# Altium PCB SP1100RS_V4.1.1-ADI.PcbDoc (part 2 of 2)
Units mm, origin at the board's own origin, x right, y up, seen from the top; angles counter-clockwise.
Board outline 126.12 x 87.13 mm, 4 copper layers (TopLayer, GND, PWR, BottomLayer); 154 components, 100 nets, 516 pads, 161 vias.
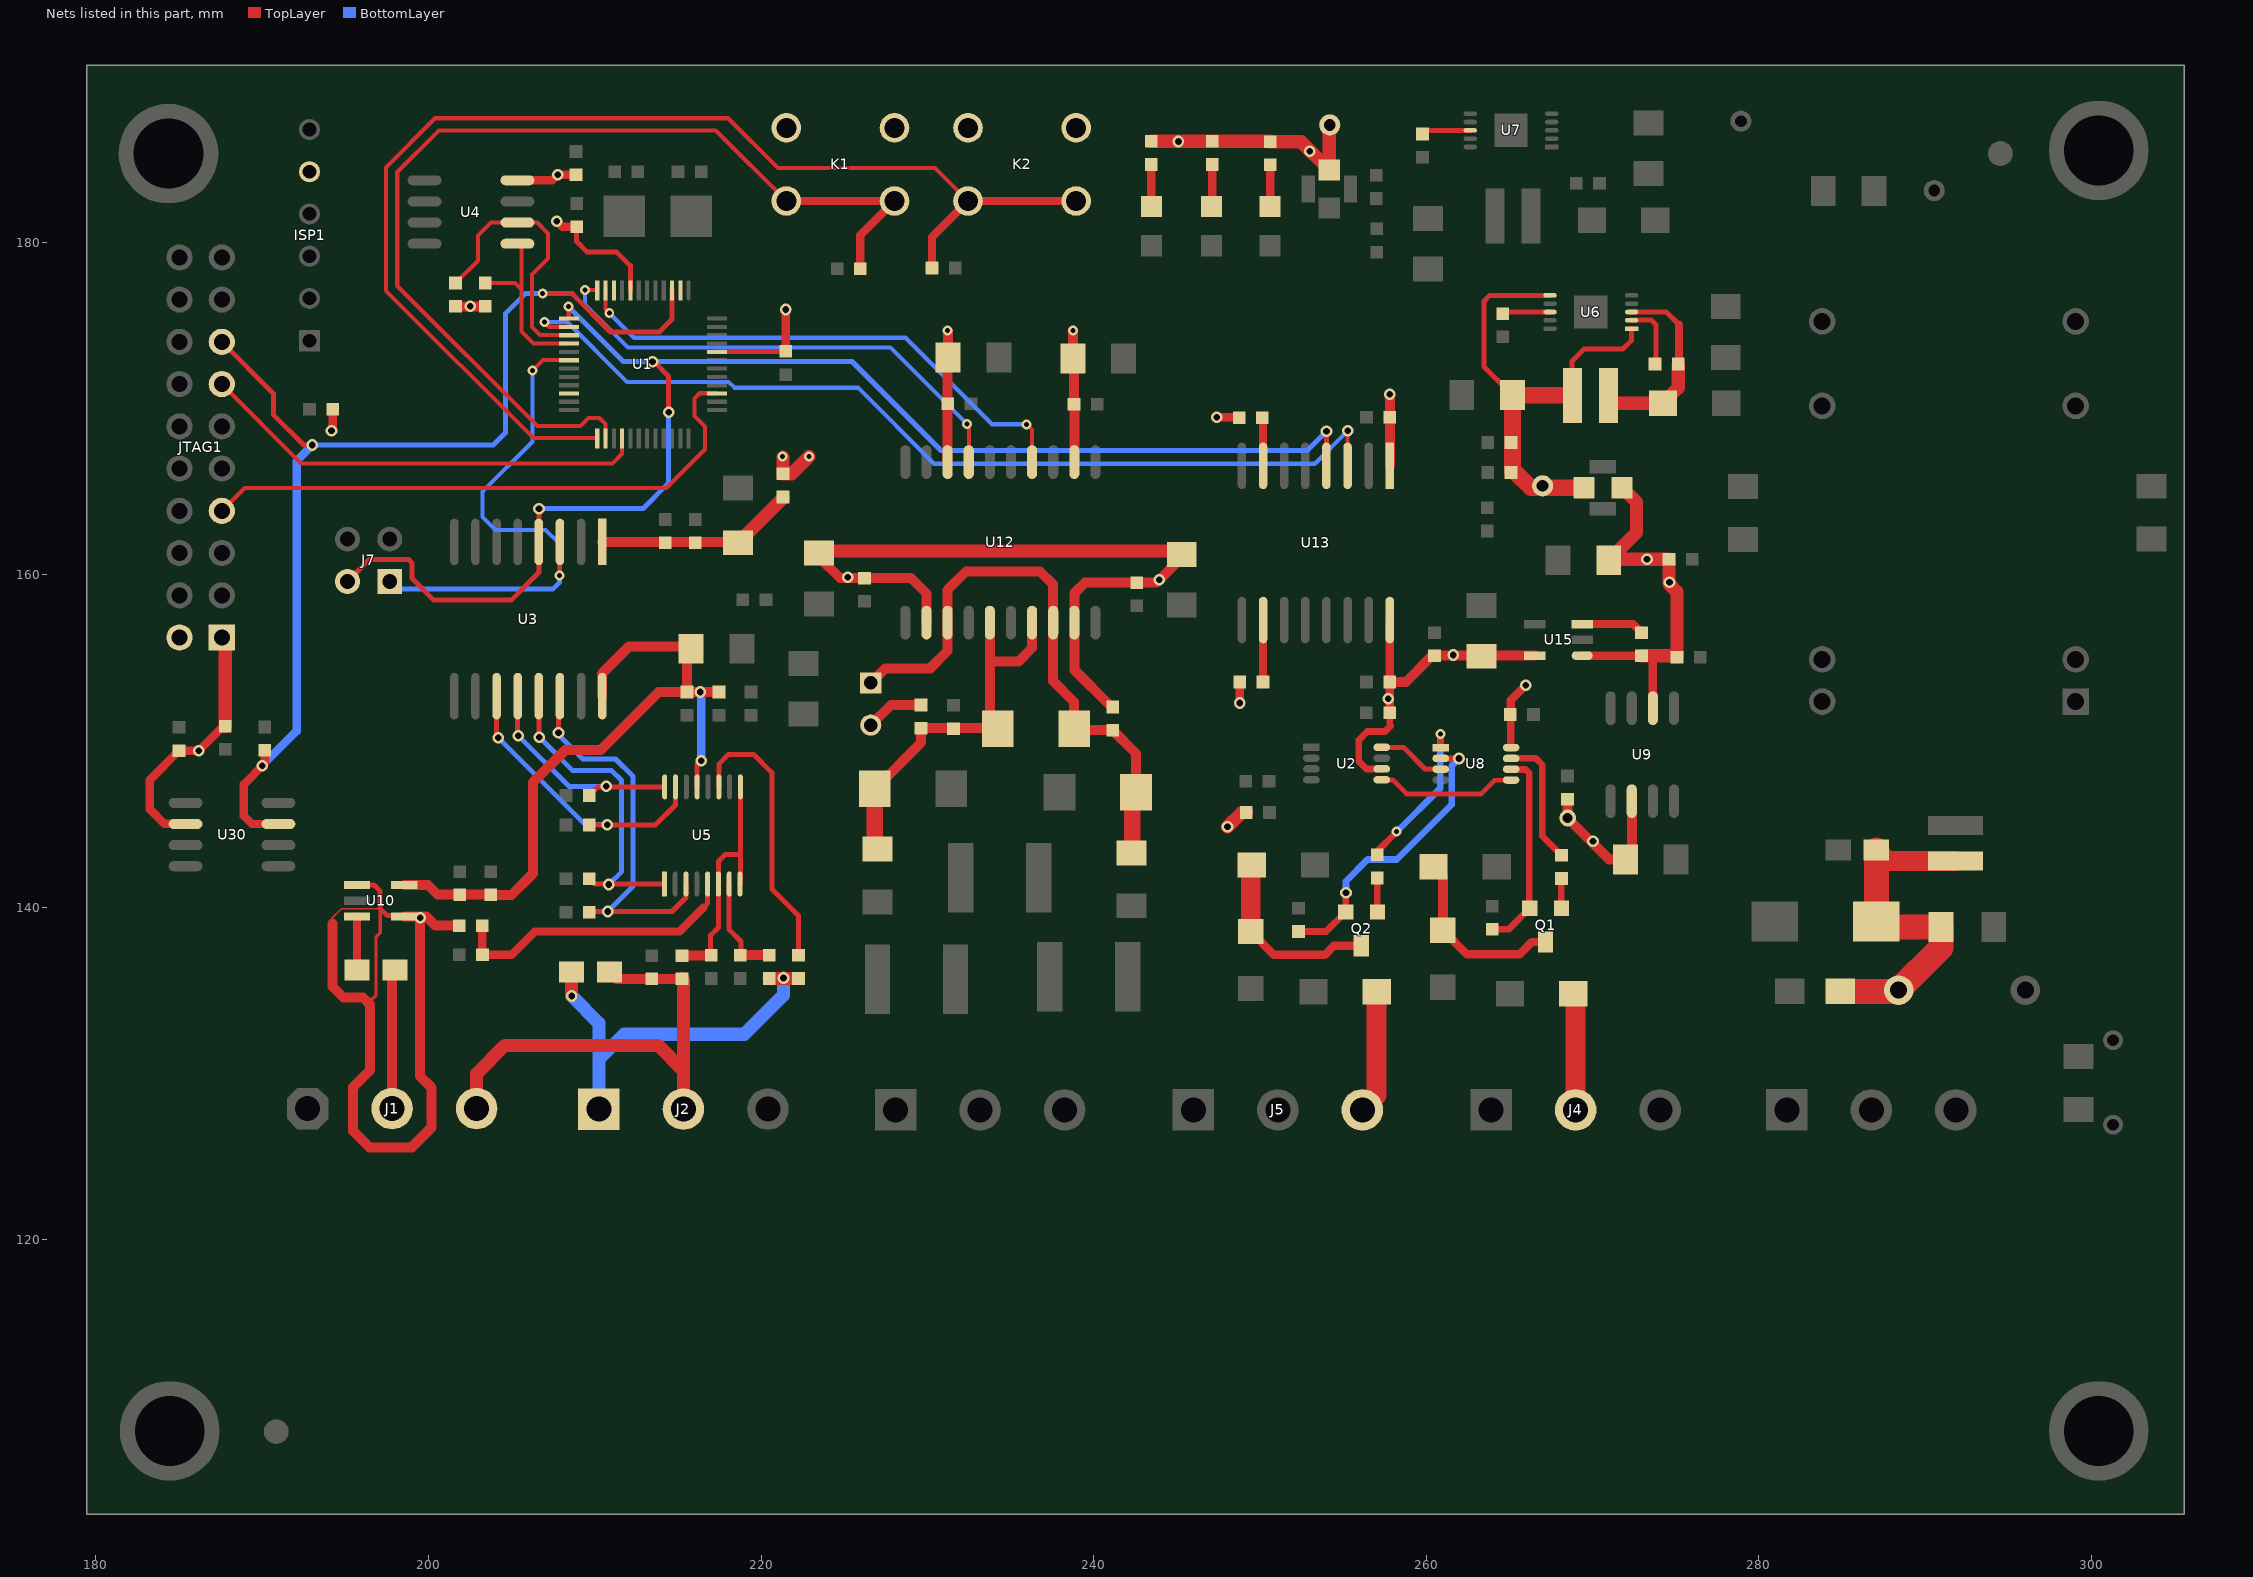
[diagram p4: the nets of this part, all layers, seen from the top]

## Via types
v1: diameter 0.7, hole 0.4, TopLayer to BottomLayer, 127 vias
v2: diameter 0.6, hole 0.3, TopLayer to BottomLayer, 30 vias
v3: diameter 1, hole 0.6, TopLayer to BottomLayer, 4 vias

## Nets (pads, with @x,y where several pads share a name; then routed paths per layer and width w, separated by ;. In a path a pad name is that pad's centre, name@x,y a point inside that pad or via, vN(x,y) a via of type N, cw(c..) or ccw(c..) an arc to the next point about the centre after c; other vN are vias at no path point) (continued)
NetC17_1: C17.1 R3.2 U5.7 | length 6.3
  TopLayer w0.3: U5.7@218.089,141.404 218.089,138.661 218.8,137.95 218.8,137.175 C17.1@218.75,137.125
  TopLayer w0.6: C17.1@218.75,137.125 220.497,137.125 R3.2@220.5,137.122
NetC18_1: C18.1 R19.2 U5.5 | length 17.7
  TopLayer w0.3: C18.1@203.247,137.153 C18.1@203.25,137.15 ; 216.538,139.988 216.789,140.239 U5.5@216.789,141.404
  TopLayer w0.5: C18.1@203.247,137.153 R19.2@203.247,138.9 ; C18.1@203.25,137.15 205,137.15 206.4,138.55 215.1,138.55 216.538,139.988
NetC19_1: C19.1 R20.2 U5.6 U5.8 U5.9 | length 15
  TopLayer w0.3: C19.1@216.972,137.097 216.975,137.1 216.975,138.325 217.439,138.789 U5.6@217.439,141.404 217.439,142.764 217.85,143.175 218.761,143.175 ; U5.8@218.739,141.404 218.761,141.426 218.761,143.175 ; U5.9@218.761,147.246 218.761,143.175
  TopLayer w0.6: R20.2@215.25,137.097 C19.1@216.972,137.097 ; C19.1@216.975,137.1 C19.1@217,137.125
NetC22_1: C22.1 U6.2 | length 4
  TopLayer w0.3: U6.2@272.318,175.306 273.543,175.306 273.805,175.044 C22.1@273.805,172.675
NetC22_2: C22.2 D49.2 L1.1 U6.3 | length 11.8
  TopLayer w0.3: U6.3@272.318,175.806 274.44,175.806 275.202,175.044
  TopLayer w0.5: C22.2@275.202,172.675 275.202,175.044
  TopLayer w0.8: L1.1@270.96,170.775 271.423,170.312 D49.2@274.236,170.312 275.157,171.233 C22.2@275.157,172.675
NetC23_1: C23.1 C51.1 FB7.1 L1.2 TP6.1 U6.1 U6.6 VA2.2 | length 29.3
  TopLayer w0.3: C23.1@265.185,170.8 263.475,172.51 263.475,176.45 263.825,176.8 U6.6@267.45,176.8 ; L1.2@268.775,170.8 268.775,172.85 269.5,173.575 271.825,173.575 272.35,174.1 U6.1@272.35,174.8
  TopLayer w1: VA2.2@265.185,166.238 C23.1@265.185,170.8 268.775,170.8 L1.2@268.8,170.775 ; VA2.2@265.375,166.15 266.292,165.233 268.76,165.233
NetC41_1: C41.1 CA11.1 D3.2 F3.2 L3.1 VR1.1 | length 21.8
  TopLayer w1.2: C41.1@287.065,143.442 287.732,142.775 L3.1@291.825,142.775
  TopLayer w1.5: F3.2@284.898,134.95 288.33,134.95 D3.2@288.405,135.025 290.952,137.572 VR1.1@290.952,138.825 287.375,138.825 CA11.1@287.05,139.15 287.065,139.165 C41.1@287.065,143.442
NetC54_1: C54.1 CA22.1 FB2.1 U9.6 | length 10.8
  TopLayer w0.6: C54.1@268.5,146.5 v3(268.5,145.375) 271,142.875 CA22.1@271.975,142.875 272.36,143.26 U9.6@272.36,146.387
  TopLayer w0.8: v1(248.05,144.85) 248.9,145.7 FB2.1@249.178,145.7
  other v1: 270.025,143.975
NetD1_2: D1.2 F1.1 Q1.3 | length 11.1
  TopLayer w0.5: F1.1@261,138.625 262.45,137.175 265.6,137.175 266.345,137.92 Q1.3@267.165,137.92
  TopLayer w0.6: D1.2@260.44,142.447 261,141.888 F1.1@261,138.625
NetD2_2: D2.2 F2.1 Q2.3 | length 11.5
  TopLayer w0.5: F2.1@249.45,138.554 250.854,137.15 253.9,137.15 254.445,137.695 Q2.3@256.098,137.695
  TopLayer w1.2: F2.1@249.45,138.554 249.45,142.482 D2.2@249.515,142.547
NetD4_2: D4.2 J4.2 | length 7
  TopLayer w1.2: D4.2@268.842,134.803 268.986,134.659 J4.2@268.986,127.823
NetD5_2: D5.2 J5.3 | length 7.5
  TopLayer w1.2: J5.3@256.159,127.823 257.017,128.681 D5.2@257.017,134.928
NetF10_1: F10.1 R41.2 T1.1 U12.13 U12.18 ZD14.1 ZD15.1 | length 36.2
  TopLayer w0.6: T1.1@226.6,153.5 227.45,154.35 230.15,154.35 231.22,155.42 U12.13@231.22,157.123 231.22,159.095 232.325,160.2 236.779,160.2 237.57,159.409 U12.18@237.57,157.123 237.57,153.605 238.825,152.35 ZD14.1@238.825,150.75 238.922,150.653 R41.2@241.15,150.653 242.55,149.253 ZD15.1@242.55,146.925 ; F10.1@242.316,142.94 F10.1@242.316,143.29
  TopLayer w1: F10.1@242.316,143.29 242.316,146.691 ZD15.1@242.55,146.925
NetF11_1: F11.1 R42.1 R76.1 U12.15 U12.17 ZD14.2 ZD16.2 | length 24.1
  TopLayer w0.6: ZD16.2@226.85,147.125 229.625,149.9 R76.1@229.625,150.775 ZD14.2@234.2,150.775 ; U12.15@233.76,157.123 233.76,154.95 ; ZD14.2@234.225,150.75 ZD14.2@234.2,150.775 ; U12.17@236.3,157.123 236.3,155.6 235.475,154.775 233.935,154.775 233.76,154.95 ; 233.76,154.95 233.76,151.215 ZD14.2@234.2,150.775
  TopLayer w1: ZD16.2@226.85,147.125 226.85,143.574 F11.1@226.949,143.475
NetLD1_A: LD1.A R18.1 | length 2.5
  TopLayer w0.5: R18.1@250.625,184.65 250.625,182.225 LD1.A@250.65,182.2
NetLD2_A: LD2.A R17.1 | length 2.5
  TopLayer w0.5: R17.1@243.475,184.675 243.475,182.191 LD2.A@243.49,182.176
NetLD3_A: LD3.A R52.1 | length 2.5
  TopLayer w0.5: LD3.A@247.115,182.151 247.125,182.161 R52.1@247.125,184.675
NetQ1_1: Q1.1 R7.1 | length 1.8
  TopLayer w0.4: Q1.1@268.13,139.952 R7.1@268.13,141.738
NetQ1_2: Q1.2 R5.1 U8.6 | length 12.1
  TopLayer w0.4: R5.1@263.975,138.675 264.948,138.675 Q1.2@266.225,139.952 266.192,139.985 266.192,148.07 265.968,148.294 U8.6@265.088,148.294
NetQ2_1: Q2.1 R13.1 | length 2
  TopLayer w0.4: Q2.1@257.063,139.727 R13.1@257.063,141.765
NetQ2_2: Q2.2 R4.1 U8.2 | length 17.5
  TopLayer w0.4: R4.1@252.325,138.55 253.981,138.55 Q2.2@255.158,139.727 255.158,140.858 v1(255.175,140.875) ; U8.2@260.858,148.944 261.969,148.944 v1(261.975,148.95)
  BottomLayer w0.4: v1(255.175,140.875) 255.175,141.575 256.475,142.875 258.225,142.875 261.525,146.175 261.525,148.5 v1(261.975,148.95)
NetR2_2: R2.2 U5.11 | length 16.9
  TopLayer w0.3: U5.11@217.461,147.246 217.461,148.611 218.05,149.2 219.55,149.2 220.65,148.1 220.65,141.1 222.25,139.5 R2.2@222.25,137.122
NetR7_2: R7.2 U8.7 | length 7.9
  TopLayer w0.4: U8.7@265.106,148.958 266.592,148.958 266.975,148.575 266.975,144.29 R7.2@268.13,143.135
NetR8_2: R8.2 U6.8 | length 2.9
  TopLayer w0.3: R8.2@264.61,175.7 264.71,175.8 U6.8@267.45,175.8
NetR11_2: R11.2 U7.8 | length 3
  TopLayer w0.3: R11.2@259.775,186.5 260,186.725 U7.8@262.65,186.725
NetR13_2: R13.2 U8.1 | length 9.6
  TopLayer w0.4: R13.2@257.063,143.162 257.063,143.388 v2(258.225,144.55) ; U8.1@260.876,149.608 v2@260.876,150.399
  BottomLayer w0.4: v2(258.225,144.55) 260.85,147.175 v2(260.85,150.425)
NetR16_2: R16.2 U10.3 | length 3.2
  TopLayer w0.5: R16.2@195.704,136.242 U10.3@195.704,139.446
NetR19_1: R19.1 U10.1 U10.4 | length 50.3
  TopLayer w0.1: 194.225,139.025 194.225,139.375 194.775,139.925 197.1,139.925
  TopLayer w0.2: 196.5,134.15 196.5,134.375 196.85,134.725 196.85,138.225 197.1,138.475 197.1,139.925
  TopLayer w0.3: U10.1@195.7,141.35 196.725,141.35 197.1,140.975 197.1,139.925 197.525,139.5 198.5,139.5 U10.4@198.55,139.45
  TopLayer w0.6: 194.225,139.025 194.225,135.25 194.9,134.575 196.075,134.575 196.5,134.15 196.5,130.225 195.475,129.2 195.475,126.55 196.45,125.575 199,125.575 200.2,126.775 200.2,129.15 199.5,129.85 v1(199.5,139.375) ; U10.4@198.55,139.45 199.875,139.45 200.425,138.9 R19.1@201.85,138.9
NetR70_1: R70.1 U13.7 | length 2.9
  TopLayer w0.5: R70.1@250.15,169.45 250.19,169.41 U13.7@250.19,166.55
NetR71_2: R71.2 U13.10 | length 3.7
  TopLayer w0.5: R71.2@250.19,153.556 U13.10@250.19,157.279
NetR72_1: R72.1 U15.3 | length 3.8
  TopLayer w0.5: U15.3@269.38,157.038 272.434,157.038 R72.1@272.95,156.522
NetR76_2: R76.2 T1.2 | length 3.5
  TopLayer w0.6: T1.2@226.6,150.96 227.812,152.172 R76.2@229.625,152.172
NetU2_5: U2.5 U8.5 | length 8.4
  TopLayer w0.3: U2.5@257.341,147.669 257.982,147.669 258.826,146.825 263.3,146.825 264.119,147.644 U8.5@265.088,147.644
NetU2_8: U2.8 U8.3 | length 4.1
  TopLayer w0.3: U2.8@257.341,149.619 258.631,149.619 259.931,148.319 U8.3@260.858,148.319
PH-CMP: J1.3 J2.2 R20.1 R21.1 R22.1 | length 28.4
  TopLayer w0.6: R21.1@210.89,136.117 211.307,135.7 R22.1@213.425,135.7 R20.1@215.25,135.7 R20.1@215.335,135.615
  TopLayer w0.8: J1.3@202.897,127.898 202.897,129.997 204.6,131.7 213.81,131.7 215.335,130.175 ; R20.1@215.25,135.7 215.335,135.615 215.335,130.175 ; J2.2@215.335,127.873 215.335,130.175
PH-INP: J1.2 R16.1 | length 8.4
  TopLayer w0.6: J1.2@197.817,127.898 197.817,136.069 R16.1@197.99,136.242
R\E\S\E\T\: JTAG1.15 R68.2 U1.3 U30.7 | length 68.7
  TopLayer w0.3: JTAG1.15@187.575,174.005 190.675,170.905 190.675,169.625 192.5,167.8 v1(193.025,167.8) ; v2(206.875,176.9) 208.65,176.9 210.95,174.6 213.889,174.6 214.642,175.353 U1.3@214.642,177.115
  TopLayer w0.5: R68.2@190.15,149.453 190.15,148.65 188.9,147.4 188.9,145.5 189.385,145.015 U30.7@190.984,145.015
  BottomLayer w0.3: v1(193.025,167.8) 203.9,167.8 204.625,168.525 204.625,173.575 204.625,175.7 205.825,176.9 v2(206.875,176.9)
  BottomLayer w0.5: v1(190,148.525) 192.075,150.6 192.075,166.85 v1(193.025,167.8)
RX485: U1.11 U12.4 | length 31.7
  TopLayer w0.25: U1.11@210.642,177.115 210.642,175.983 v2(210.875,175.75) ; v2(235.975,169.05) 236.3,168.725 U12.4@236.3,166.775
  BottomLayer w0.25: v2(210.875,175.75) 212.375,174.25 228.7,174.25 233.9,169.05 v2(235.975,169.05)
SCK0: U1.22
SCK1: J7.2 U1.13 U3.4 U13.4 | length 86.8
  TopLayer w0.25: v2(208.425,176.125) 208.442,176.108 U1.13@208.442,175.415
  TopLayer w0.3: J7.2@195.135,159.6 196.46,160.925 198.8,160.925 199.025,160.7 199.025,159.775 200.325,158.475 204.975,158.475 206.64,160.14 U3.4@206.64,161.975 206.64,163.965 v1(206.65,163.975) ; v1(213.475,172.8) 213.575,172.8 214.45,171.925 v1(214.45,169.775) ; U13.4@254,166.55 v1(254,168.625)
  BottomLayer w0.3: v1(206.65,163.975) 212.9,163.975 214.45,165.525 v1(214.45,169.775) ; v2(208.425,176.125) 211.725,172.825 v1@213.475,172.825 ; v1(213.475,172.8) v1@213.475,172.825 ; v1(254,168.625) 252.85,167.475 230.825,167.475 225.475,172.825 v1@213.475,172.825
SCL: R14.1 U1.15 U4.6 | length 16.7
  TopLayer w0.25: R14.1@201.631,177.541 202.975,178.885 202.975,180.4 203.754,181.179 U4.6@205.355,181.179 206.546,181.179 207.2,180.525 207.2,179.025 206.225,178.05 206.225,174.9 206.71,174.415 U1.15@208.442,174.415
SDA: R15.1 U1.16 U4.5 | length 10.9
  TopLayer w0.25: R15.1@203.409,177.541 205.204,177.541 205.6,177.144 ; U4.5@205.355,179.909 205.6,179.664 205.6,177.144 ; U1.16@208.442,173.915 206.31,173.915 205.6,174.625 205.6,177.144
SPI_CS: R6.2 U3.14 U5.3 | length 23.6
  TopLayer w0.3: v1(207.825,150.5) 207.825,152.619 U3.14@207.91,152.704 ; R6.2@209.672,139.7 209.722,139.75 v1(210.775,139.75) 214.65,139.75 215.489,140.589 U5.3@215.489,141.404
  BottomLayer w0.3: v1(207.825,150.5) 207.825,150.375 209.275,148.925 211.25,148.925 212.3,147.875 212.3,141.275 v1(210.775,139.75)
SPI_DIN: R10.2 U3.12 U5.16 | length 13.7
  TopLayer w0.3: U3.12@205.37,152.704 205.37,150.355 v1(205.4,150.325) ; R10.2@209.672,146.725 210.193,147.246 U5.16@214.211,147.246
  BottomLayer w0.3: v1(205.4,150.325) 208.45,147.275 v1(210.7,147.275)
SPI_DOUT: R12.2 U3.11 U5.15 | length 18
  TopLayer w0.3: U3.11@204.1,152.704 204.1,150.3 v1(204.2,150.2) ; R12.2@209.672,144.95 213.65,144.95 214.861,146.161 U5.15@214.861,147.246
  BottomLayer w0.3: v1(204.2,150.2) 209.425,144.975 v1(210.75,144.975)
SPI_SCLK: R9.2 U3.13 U5.1 | length 19.7
  TopLayer w0.3: U3.13@206.64,152.704 206.64,150.26 v1(206.675,150.225) ; R9.2@209.672,141.725 209.993,141.404 U5.1@214.189,141.404
  BottomLayer w0.3: v1(206.675,150.225) 208.675,148.225 211.025,148.225 211.625,147.625 211.625,142.15 v1(210.85,141.375)
SSEL0: U1.10
SSEL1: J7.1 U1.18 U3.3 | length 32.7
  TopLayer w0.25: v2(206.25,172.275) 206.89,172.915 U1.18@208.442,172.915 ; v2(207.875,159.95) 207.91,159.985 U3.3@207.91,161.975
  BottomLayer w0.25: v2(206.25,172.275) 206.25,168 203.25,165 203.25,163.475 204.025,162.7 207.05,162.7 207.875,161.875 v2(207.875,159.95)
  BottomLayer w0.3: J7.1@197.675,159.6 198.125,159.15 207.5,159.15 207.875,159.525 v2(207.875,159.95)
SSEL1_A: U1.2
SSEL1_B: U1.14 U13.3 | length 56.3
  TopLayer w0.25: v2(206.975,175.2) 207.26,174.915 U1.14@208.442,174.915 ; U13.3@255.27,166.55 255.27,168.645 v1(255.275,168.65)
  BottomLayer w0.25: v2(206.975,175.2) 208.35,175.2 211.95,171.6 218.05,171.6 218.4,171.25 225.825,171.25 230.4,166.675 253.3,166.675 v1(255.275,168.65)
SW_S1: K1.2 R73.2 U1.26 | length 61.7
  TopLayer w0.25: U1.26@210.642,168.215 210.642,169.058 210.275,169.425 209.625,169.425 209.15,168.95 206.55,168.95 198.125,177.375 198.125,184.225 200.625,186.725 217.276,186.725 K1.2@221.526,182.475
  TopLayer w0.5: K1.2@221.526,182.475 K1.2@228.026,182.475 225.975,180.424 R73.2@225.975,178.4
SW_S2: K2.2 R74.2 U1.25 | length 73.5
  TopLayer w0.25: U1.25@210.142,168.215 206.31,168.215 197.45,177.075 197.45,184.5 200.4,187.45 218.025,187.45 221.025,184.45 230.473,184.45 K2.2@232.448,182.475
  TopLayer w0.5: R74.2@230.278,178.45 230.278,180.305 K2.2@232.448,182.475 K2.2@238.948,182.475
SWDIO: JTAG1.7 U1.39 | length 35.4
  TopLayer w0.25: JTAG1.7@187.575,163.845 188.955,165.225 214.3,165.225 216.625,167.55 216.625,168.925 216,169.55 216,170.6 216.315,170.915 U1.39@217.342,170.915
SWO: JTAG1.13 U1.28 | length 27.2
  TopLayer w0.25: JTAG1.13@187.575,171.465 192.34,166.7 211.075,166.7 211.65,167.275 U1.28@211.65,168.2
TP-IN+: J2.1 R2.1 R3.1 R21.2 | length 24.4
  TopLayer w0.8: v1@208.604,134.696 R21.2@208.604,136.117 ; R3.1@220.5,135.725 R2.1@222.25,135.725
  BottomLayer w0.8: v1(208.625,134.675) 210.255,133.045 210.255,130.855 ; J2.1@210.255,127.873 210.255,130.855 ; v1(221.35,135.75) 221.35,134.725 219,132.375 211.775,132.375 210.255,130.855
TX485: U1.12 U12.7 | length 29.9
  TopLayer w0.25: v2(209.425,177.125) 209.435,177.115 U1.12@210.142,177.115 ; v2(232.375,169.075) 232.5,168.95 232.5,166.785 U12.7@232.49,166.775
  BottomLayer w0.25: v2(209.425,177.125) 209.425,176.25 212,173.675 227.775,173.675 v2(232.375,169.075) v2@232.375,169.025
V330_A: C5.1 C55.1 C57.1 CA25.1 R71.1 U2.6 U13.16 U15.5 | length 22
  TopLayer w0.4: U2.6@257.341,148.319 256.406,148.319 255.95,148.775 255.95,150.075 256.45,150.575 257.525,150.575 257.875,150.925 257.8,151 C5.1@257.8,151.7
  TopLayer w0.5: v1(248.793,152.286) R71.1@248.793,153.556 ; C5.1@257.81,151.725 C57.1@257.81,153.556 U13.16@257.81,157.279
  TopLayer w0.6: C57.1@257.81,153.556 258.781,153.556 C55.1@260.35,155.125 ; C55.1@260.5,155.125 260.513,155.138 U15.5@266.53,155.138
  other v1: 257.725,152.55 261.625,155.175
V330_D: C3.1 C4.1 C27.1 C28.1 C43.1 C44.1 C56.1 CA13.1 CA14.1 FB4.2 FB5.1 ISP1.5 JTAG1.1 JTAG1.2 K1.1 K2.1 R1.2 R14.2 R15.2 R17.2 R18.2 R52.2 R69.2 R70.2 TP5.1 U1.8 U1.44 U4.8 U12.2 U12.8 U13.1 U30.2 | length 75.3
  TopLayer w0.3: C4.1@208.911,180.925 208.911,180.036 209.546,179.401 211.324,179.401 212.142,178.583 U1.8@212.142,177.115 ; U1.44@217.342,173.432 C3.1@221.625,173.432
  TopLayer w0.5: U30.2@185.396,145.015 185.386,145.025 184.125,145.025 183.25,145.9 183.25,147.675 C27.1@185,149.425 v1(186.2,149.425) 187.672,150.897 R69.2@187.775,150.897 ; v1@194.247,168.722 R1.2@194.247,169.95 ; U4.8@205.355,183.719 207.444,183.719 v1(207.775,184.05) C28.1@208.85,184.05 ; v1(207.725,181.25) 208.05,180.925 C4.1@208.911,180.925 ; C3.1@221.484,173.432 v1(221.484,175.95) ; v1(247.396,169.471) R70.2@248.793,169.471
  TopLayer w0.6: R14.2@201.631,176.144 R15.2@203.409,176.144 ; U12.8@231.22,166.775 CA14.1@231.22,173.29 ; CA14.1@231.25,173.075 v2@231.25,174.65 ; v2(238.75,174.675) CA13.1@238.75,173 238.825,172.925 C43.1@238.825,170.25 ; U12.2@238.84,166.775 C43.1@238.84,170.25 ; v1(257.8,170.85) 257.8,170.7 257.81,170.69 C56.1@257.81,169.471 U13.1@257.81,166.55
  TopLayer w0.8: JTAG1.1@187.575,156.225 187.775,156.025 R69.2@187.775,150.897 ; v2@221.325,167.075 FB5.1@221.325,166.075 221.85,166.075 v2(222.875,167.1) ; R17.2@243.475,186.072 250.6,186.072 R18.2@250.625,186.047 252.5,186.047 252.5,186.013 FB4.2@254.167,184.346 254.167,187.017 TP5.1@254.2,187.05
  other v1: 194.175,168.65 202.525,176.15 253,185.475 245.1,186.05
  other v2: 221.3,167.1 231.225,174.675
V500_A: C2.1 C52.1 C53.1 CA23.1 FB7.2 R72.2 U8.8 U9.2 U15.1 | length 27.8
  TopLayer w0.457: U8.8@265.088,149.594 C2.1@265.088,151.575
  TopLayer w0.5: C2.1@265.049,151.593 265.075,151.619 265.075,152.45 v1(265.975,153.35) v1@266.025,153.4 ; U15.1@269.38,155.138 272.937,155.138 R72.2@272.95,155.125 ; U9.2@273.63,151.975 273.63,154.795
  TopLayer w0.8: CA23.1@270.975,160.875 CA23.1@271.025,160.925 ; FB7.2@271.771,165.233 272.65,164.354 272.65,162.55 CA23.1@271.025,160.925 ; R72.2@272.95,155.125 275,155.125 C53.1@275.075,155.05 275.075,158.975 274.6,159.45 C52.1@274.6,160.925 CA23.1@271.025,160.925
  other v1: 274.625,159.55 273.275,160.925
VCC330: C1.1 C9.2 CA1.1 FB5.2 U3.1 | length 12.1
  TopLayer w0.6: U3.1@210.45,161.975 218.575,161.975 CA1.1@218.625,161.925
  TopLayer w0.8: CA1.1@218.625,161.925 221.325,164.625 FB5.2@221.325,164.678
VCC330_ISO: C8.1 C12.1 C14.1 CA2.1 FB1.1 U3.16 U5.13 U10.5 | length 43.3
  TopLayer w0.3: U5.13@216.161,147.246 216.161,148.586 v1(216.4,148.825)
  TopLayer w0.6: U10.5@198.55,141.35 199.975,141.35 200.55,140.775 203.725,140.775 C14.1@203.75,140.75 205,140.75 206.275,142.025 206.275,147.5 208.225,149.45 210.35,149.45 213.85,152.95 C8.1@215.55,152.95 ; U3.16@210.45,152.704 210.45,154.075 212.05,155.675 215.675,155.675 CA2.1@215.8,155.55 215.55,155.3 C8.1@215.55,152.95 ; FB1.1@217.475,152.95 v1(216.35,152.95) C8.1@215.55,152.95
  BottomLayer w0.5: v1(216.4,148.825) v1@216.4,152.9
VCC_COM: C45.1 C46.2 CA15.1 CA16.1 R41.1 U12.12 U12.19 | length 46.4
  TopLayer w0.6: CA15.1@223.5,161.05 224.753,159.797 C45.1@226.225,159.797 229.028,159.797 229.95,158.875 U12.12@229.95,157.123 ; R41.1@241.15,152.05 241.075,152.05 238.84,154.285 U12.19@238.84,157.123 238.84,158.89 239.475,159.525 C46.2@242.6,159.525 243.775,159.525 CA16.1@245.3,161.05
  TopLayer w0.8: CA15.1@223.5,161.05 223.875,161.425 244.925,161.425 CA16.1@245.3,161.05
  other v1: 243.95,159.7 225.225,159.85
pads on no net: J1.1 J2.3 JTAG1.3 JTAG1.5 JTAG1.11 JTAG1.17 JTAG1.19 U1.1 U1.19 U1.20 U1.21 U1.23 U1.24 U1.27 U1.31 U1.36 U1.40 U1.42 U1.43 U1.45 U1.48 U3.7 U5.2 U5.4 U6.5 U6.7 U6.9 U7.5 U7.7 U7.9 U9.1 U9.3 U9.5 U9.7 U9.8 U11.9 U11.11 U13.6 U13.11 U15.4 U30.4 U30.5 U30.6 U30.8

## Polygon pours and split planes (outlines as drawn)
GND_ISO on BottomLayer "Top Layer-No Net" (hatched 90Degree grid 0.3 track 0.3, remove dead copper, pour order 14): 222.8,133.45 222.8,156.3 222.875,156.375 214.975,156.375 211.525,152.925 211,152.4 200.475,152.4 200.475,144.2 201.75,142.925 202,142.675 202,135.85 202,133.55 202.125,133.425
NetR19_1 on BottomLayer "Top Layer-No Net" (hatched 90Degree grid 0.3 track 0.3, remove dead copper, pour order 11): 196.325,125.2 199.125,125.2 200.475,126.55 200.475,139.625 199.8,140.3 197.575,140.3 197.475,140.4 197.475,142.05 197.45,142.075 195.45,142.075 194.725,141.35 194.15,140.775 194.15,135.175 194.15,134.8 195.45,133.5 195.45,126.075 196.3,125.225
EARTH on BottomLayer "Top Layer-No Net" (hatched 90Degree grid 0.3 track 0.3, remove dead copper, pour order 16): 180.275,123.3 304.425,123.3 304.425,104.573 180.3,104.573 180.275,104.525
IAGND on BottomLayer "Top Layer-No Net" (hatched 90Degree grid 0.3 track 0.3, remove dead copper, pour order 18): 247.2,159.575 277.575,159.575 277.65,159.65 277.65,137.275 277.775,137.15 247.6,137.15 247.2,137.55
GND on BottomLayer "Top Layer-No Net" (hatched 90Degree grid 0.3 track 0.3, remove dead copper, pour order 20): 196.225,163.625 259.05,163.625 259.125,163.7 259.125,173 256.325,175.8 225.35,175.8 223.45,177.7 196.225,177.7
GND_ISO on TopLayer "Top Layer-No Net" (hatched 90Degree grid 0.3 track 0.3, remove dead copper, pour order 14): 222.875,133.7 222.875,156.55 222.95,156.625 215.05,156.625 211.6,153.175 211.075,152.65 200.55,152.65 200.55,144.45 201.825,143.175 202.075,142.925 202.075,136.1 202.075,133.8 202.2,133.675
+24V on TopLayer "Top Layer-No Net" (hatched 90Degree grid 0.3 track 0.3, remove dead copper, pour order 12): 285.025,173.75 285.025,185.75 284.95,185.825 280.225,185.825 280.2,185.85 280.2,175.025 281.45,173.775
GND on TopLayer "Top Layer-No Net" (hatched 90Degree grid 0.3 track 0.3, remove dead copper, pour order 13): 283.375,172.1 289.801,172.1 293.232,168.52 293.866,167.858 298.5,167.858 298.5,164.985 297.604,164.05 292.817,164.05 288.992,168.041 288.664,168.383 283.419,168.383
24VGND_IN on TopLayer "Top Layer-No Net" (hatched 90Degree grid 0.3 track 0.3, remove dead copper, pour order 14): 296.925,161.325 296.925,150.2 296.95,150.175 296.95,149.65 296.925,149.625 301.45,149.625 301.45,161.175 301.3,161.325
NetC02_2 on TopLayer "Top Layer-No Net" (hatched 90Degree grid 0.3 track 0.3, remove dead copper, pour order 15): 281.65,157.3 281.65,151.5 282.8,150.35 283.175,149.975 285.475,149.975 286.8,148.65 290.9,148.65 290.9,149.15 288.1,151.95 285.525,154.525 285.525,157.25
IAGND on TopLayer "Top Layer-No Net" (hatched 90Degree grid 0.3 track 0.3, remove dead copper, pour order 17): 247.1,159.45 277.475,159.45 277.55,159.525 277.55,137.15 277.675,137.025 247.5,137.025 247.1,137.425
GND on TopLayer "Top Layer-No Net" (hatched 90Degree grid 0.3 track 0.3, remove dead copper, pour order 19): 195.95,163.35 258.775,163.35 258.85,163.425 258.85,172.725 256.05,175.525 225.075,175.525 223.175,177.425 195.95,177.425
IAGND on GND (split plane): 277.923,136.416 276.916,135.409 276.866,135.348 276.829,135.279 276.806,135.203 276.798,135.125 276.798,124.352 242.052,124.352 242.052,130.759 246.734,135.441 246.784,135.502 246.821,135.571 246.844,135.647 246.852,135.725 246.852,160.173 258.225,160.173 258.303,160.181 258.379,160.204 258.448,160.241 258.509,160.291 260.316,162.098 277.923,162.098
GND_COM on GND (split plane): 246.048,135.891 241.366,131.209 241.316,131.148 241.279,131.079 241.256,131.003 241.248,130.925 241.248,124.352 223.902,124.352 223.902,160.173 246.048,160.173
24VGND_IN on GND (split plane): 305.059,124.352 277.602,124.352 277.602,134.959 278.609,135.966 278.659,136.027 278.696,136.096 278.719,136.172 278.727,136.25 278.727,159.475 305.059,159.475
GND on GND (split plane): 305.059,167.15 278.35,167.15 278.35,162.899 278.325,162.902 260.877,162.902 260.877,174.225 260.869,174.303 260.846,174.379 260.809,174.448 260.759,174.509 258.259,177.009 258.198,177.059 258.129,177.096 258.053,177.119 257.975,177.127 249.9,177.127 249.822,177.119 249.746,177.096 249.677,177.059 249.616,177.009 249.566,176.948 249.529,176.879 249.506,176.803 249.498,176.725 249.506,176.647 249.529,176.571 249.566,176.502 249.616,176.441 249.677,176.391 249.746,176.354 249.822,176.331 249.9,176.323 257.809,176.323 260.073,174.059 260.073,162.894 260.072,162.894 260.014,162.877 259.996,162.871 259.927,162.834 259.866,162.784 258.059,160.977 217.5,160.977 217.422,160.969 217.346,160.946 217.277,160.909 217.216,160.859 213.434,157.077 194.175,157.077 194.097,157.069 194.021,157.046 193.952,157.009 193.891,156.959 193.841,156.898 193.804,156.829 193.781,156.753 193.773,156.675 193.773,143.641 191.134,141.002 179.96,141.002 179.96,190.139 305.059,190.139
GND_ISO on GND (split plane): 223.098,124.352 205.775,124.352 205.775,132.125 200.725,132.125 200.625,132.225 200.625,142.325 200.6,142.3 195.025,142.3 193.95,141.225 193.95,132.05 188.1,132.05 188.1,124.352 179.96,124.352 179.96,140.198 191.3,140.198 191.378,140.206 191.454,140.229 191.523,140.266 191.584,140.316 194.459,143.191 194.509,143.252 194.546,143.321 194.569,143.397 194.577,143.475 194.577,156.273 213.6,156.273 213.678,156.281 213.754,156.304 213.823,156.341 213.884,156.391 217.666,160.173 223.098,160.173
no net on GND (split plane): 305.059,104.032 179.96,104.032 179.96,123.548 188.123,123.548 188.125,123.525 188.15,123.5 205.7,123.5 205.748,123.548 241.515,123.548 241.572,123.531 241.65,123.523 241.728,123.531 241.785,123.548 305.059,123.548
+24V on PWR (split plane): 305.059,167.15 278.163,167.15 278.163,162.477 265.002,162.477 265.002,176.4 264.994,176.465 264.968,176.526 264.928,176.578 264.876,176.618 264.853,176.628 264.843,176.651 264.803,176.703 264.751,176.743 264.69,176.769 264.625,176.777 259.402,176.777 259.402,190.139 305.059,190.139
V500_A on PWR (split plane): 278.148,149.302 265.002,149.302 265.002,161.973 278.148,161.973
V330_A on PWR (split plane): 264.498,149.154 261.646,146.302 246.752,146.302 246.752,160.648 264.498,160.648
+24V_IN on PWR (split plane): 305.059,124.277 241.902,124.277 241.902,130.771 246.678,135.547 246.718,135.599 246.744,135.66 246.752,135.725 246.752,136.123 278.4,136.123 278.465,136.131 278.526,136.157 278.578,136.197 278.618,136.249 278.644,136.31 278.652,136.375 278.652,148.945 278.669,148.985 278.677,149.05 278.669,149.115 278.652,149.155 278.652,159.475 305.059,159.475
NetC54_1 on PWR (split plane): 278.148,136.627 246.752,136.627 246.752,145.798 261.75,145.798 261.815,145.806 261.876,145.832 261.928,145.872 264.854,148.798 278.148,148.798
V330_D on PWR (split plane): 258.898,176.525 258.906,176.46 258.932,176.399 258.972,176.347 259.024,176.307 259.085,176.281 259.15,176.273 264.498,176.273 264.498,162.225 264.498,161.152 224.9,161.152 224.835,161.144 224.774,161.118 224.722,161.078 223.92,160.277 214.975,160.277 214.897,160.269 214.821,160.246 214.752,160.209 214.691,160.159 209.159,154.627 179.96,154.627 179.96,190.139 258.898,190.139
VCC_COM on PWR (split plane): 246.248,135.829 241.472,131.053 241.432,131.001 241.406,130.94 241.398,130.875 241.398,124.277 224.404,124.277 224.327,124.354 224.327,159.585 224.334,159.591 224.384,159.652 224.421,159.721 224.444,159.797 224.452,159.875 224.444,159.953 224.421,160.029 224.409,160.052 225.004,160.648 246.248,160.648
no net on PWR (split plane): 305.059,104.032 179.96,104.032 179.96,123.773 188.108,123.773 188.125,123.525 188.15,123.5 205.7,123.5 205.775,123.575 205.775,123.773 241.503,123.773 241.524,123.757 241.585,123.731 241.65,123.723 241.715,123.731 241.776,123.757 241.797,123.773 305.059,123.773
VCC330_ISO on PWR (split plane): 223.823,124.277 205.775,124.277 205.775,132.125 200.725,132.125 200.625,132.225 200.625,142.325 200.6,142.3 195.025,142.3 193.95,141.225 193.95,132.05 188.1,132.05 188.1,124.277 179.96,124.277 179.96,153.823 209.325,153.823 209.403,153.831 209.479,153.854 209.548,153.891 209.609,153.941 215.141,159.473 223.823,159.473

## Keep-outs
KeepOutLayer:
  lines w0.3: 179.442,103.522 179.442,190.522 192.442,190.522 292.442,190.522 305.442,190.522 305.442,103.522 292.442,103.522 192.442,103.522 179.442,103.522

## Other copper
GND (plane layer: these items are gaps in the copper):
  pour cut-out: 188.1,123.9 188.1,132.05 193.95,132.05 193.95,141.225 195.025,142.3 200.6,142.3 200.625,142.325 200.625,132.225 200.725,132.125 205.775,132.125 205.775,123.575 205.7,123.5 188.15,123.5 188.125,123.525
  pour cut-out: 278.35,167.15 306.65,167.15 306.7,167.2 306.7,159.65 306.875,159.475 278.5,159.475 278.35,159.625
  lines w0.5: 223.5,160.575 246.45,160.575
  lines w0.8: 179.425,140.6 191.3,140.6 194.175,143.475 194.175,156.675 213.6,156.675 217.5,160.575 223.5,160.575 ; 179.525,123.95 305.45,123.95 ; 223.5,124 223.5,160.575 ; 241.65,123.925 241.65,130.925 246.45,135.725 246.45,160.575 ; 249.9,176.725 257.975,176.725 260.475,174.225 260.475,162.525 ; 277.2,123.95 277.2,135.125 278.325,136.25 278.325,162.5 260.15,162.5 258.225,160.575 223.5,160.575 ; 278.275,162.425 305.375,162.425 305.625,162.675 ; 305.525,181.05 305.65,180.925
PWR (plane layer: these items are gaps in the copper):
  pour cut-out: 188.1,123.9 188.1,132.05 193.95,132.05 193.95,141.225 195.025,142.3 200.6,142.3 200.625,142.325 200.625,132.225 200.725,132.125 205.775,132.125 205.775,123.575 205.7,123.5 188.15,123.5 188.125,123.525
  pour cut-out: 278.163,167.15 306.463,167.15 306.513,167.2 306.513,159.65 306.688,159.475 278.313,159.475 278.163,159.625
  lines w0.5: 179.492,124.025 305.442,124.025 ; 224.3,124.025 224.075,124.25 224.075,160.075 224.9,160.9 246.5,160.9 ; 241.65,123.975 241.65,130.875 246.5,135.725 246.5,160.9 ; 246.5,146.05 261.75,146.05 264.75,149.05 ; 246.525,136.375 278.4,136.375 278.4,162.225 264.75,162.225 ; 259.15,190.699 259.15,176.525 264.625,176.525 ; 264.75,160.9 246.5,160.9 ; 264.75,176.4 264.75,162.225 ; 278.3,162.225 305.4,162.225 ; 278.425,149.05 264.75,149.05 ; 264.75,149.05 264.75,162.225
  lines w0.8: 179.442,154.225 209.325,154.225 214.975,159.875 224.05,159.875

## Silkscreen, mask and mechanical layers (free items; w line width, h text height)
TopOverlay:
  lines w0.3: 225.171,110.874 226.187,113.033 227.838,113.033 ; 226.822,110.874 227.838,113.033 ; 227.838,113.75 227.838,113.033 ; 228.473,110.874 229.489,113.033 227.838,113.033 ; 243.078,110.874 244.094,113.033 245.745,113.033 ; 244.729,110.874 245.745,113.033 ; 245.688,113.158 245.688,113.875 ; 246.38,110.874 247.396,113.033 245.745,113.033 ; 271.145,110.874 272.161,113.033 273.812,113.033 ; 272.796,110.874 273.812,113.033 ; 273.763,113.083 273.763,113.8 ; 274.447,110.874 275.463,113.033 273.812,113.033 ; 288.711,110.674 289.727,112.833 291.378,112.833 ; 290.362,110.674 291.378,112.833 ; 291.313,112.958 291.313,113.675 ; 292.013,110.674 293.029,112.833 291.378,112.833
  text "MISO" at 193.425,163.975 h0.8
  text "MOSI" at 197.125,163.975 h0.8
  text "SCS" at 196.875,157.25 h0.8
  text "SCK" at 193.775,157.225 h0.8
  text "+" at 288.425,141 h0.8
  text "+" at 228.092,129.54 h0.8 r180
  text "NC" at 191.757,122.045 h1.5 r270
  text "CMP" at 202.407,121.945 h1.5 r270
  text "Temp+" at 209.407,121.945 h1.5 r270
  text "NC" at 220.132,121.945 h1.5 r270
  text "INP" at 197.182,121.895 h1.5 r270
  text "Temp-" at 214.757,121.895 h1.5 r270
  text "EARTH" at 227.025,121.895 h1.5 r270
  text "485D-" at 232.105,121.895 h1.5 r270
  text "485D+" at 237.312,121.895 h1.5 r270
  text "EARTH" at 244.831,121.895 h1.5 r270
  text "A(MA)-" at 249.987,121.895 h1.5 r270
  text "A(MA)+" at 255.27,121.895 h1.5 r270
  text "B(MA)-" at 262.915,121.895 h1.5 r270
  text "B(MA)+" at 268.3,121.895 h1.5 r270
  text "EARTH" at 273.075,121.895 h1.5 r270
  text "+24V" at 280.625,121.85 h1.5 r270
  text "GND" at 285.875,121.85 h1.5 r270
  text "EARTH" at 290.692,121.695 h1.5 r270
  text "Sanpell_SP1100RS_V4.1.1 2017.11" at 219.85,106.9 h1
Mechanical1:
  lines w0.3: 181.014,185.323 309.298,185.323 ; 181.086,108.522 309.672,108.522 ; 184.442,108.522 184.442,195.483 ; 300.442,108.522 300.442,195.692

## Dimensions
184.442,108.522 to 184.37,185.323 on Mechanical1
300.442,108.522 to 184.442,108.522 on Mechanical1
192.442,103.522 to 179.442,190.522 on Mechanical1
179.442,103.522 to 305.442,103.522 on Mechanical1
